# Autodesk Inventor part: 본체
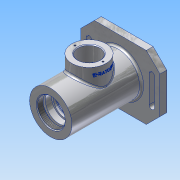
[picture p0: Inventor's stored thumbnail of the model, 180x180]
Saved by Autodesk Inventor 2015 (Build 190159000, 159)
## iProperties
Created: 2017-10
Part Number: 본체
Material: 알루미늄 6061
Document SubType Name: Modeling
Designer: Administrator
Density: 2.7 g/cm^3
Appearance: 알루미늄 - 평지
Mass: 737.992 g
Surface Area: 652.652 cm^2
Volume: 273.33 cm^3
Author: Administrator
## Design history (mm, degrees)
sketch "스케치1"
  geometry: C1 r 31 at (0, 0); 1 further point
  constraints: 1 centre point, 1 coincident
  dimensions: "d0" = 62 diameter of C1
extrude "돌출1" new body sketch "스케치1" stored distance "d1" = 115; taper "d2" = 0 deg
sketch "스케치2"
  geometry: L1 (47, 58)-(-47, 58); L2 (-47, 58)-(-47, -58); L3 (-47, -58)-(47, -58); L4 (47, -58)-(47, 58); 3 further points
  constraints: 8 end point, 2 midpoint, 2 parallel, 1 horizontal, 1 horizontal alignment, 1 perpendicular, 1 vertical alignment
  dimensions: "d3" = 94 distance between parallel lines of L2 L4; "d4" = 116 distance between parallel lines of L3 L1
extrude "돌출2" join sketch "스케치2" distance "d5" = 13; taper "d6" = 0 deg
sketch "스케치3"
  geometry: L1 (47, 58)-(-47, 58) reference; L2 (-47, 58)-(-47, -58) reference; L3 (-47, -58)-(47, -58) reference; L4 (47, -58)-(47, 58) reference; C1 r 35 at (0, 0); 1 further point
  constraints: 1 centre point, 1 coincident
  dimensions: "d7" = 70 diameter of C1
extrude "돌출3" cut sketch "스케치3" distance "d8" = 3; taper "d9" = 0 deg
node "작업 평면1"
sketch "스케치4"
  geometry: L1 (31, 57.5)-(-31, 57.5) reference; C1 r 25 at (0, 1.5); 1 further point
  constraints: 1 centre point, 1 vertical alignment
  dimensions: "d11" = 50 diameter of C1; "d12" = 56 distance from line of C1.centre L1
extrude "돌출4" join sketch "스케치4" stored distance "d13" = 3; taper "d14" = 0 deg
sketch "스케치5"
  geometry: L1 (-35, -57.5)-(35, -57.5) reference; L2 (22, -57.5)-(16, -43.5); L3 (16, -43.5)-(12.5, -43.5); L4 (12.5, -43.5)-(12.5, -36.2); L5 (12.5, -36.2)-(10, -36.2); L6 (10, -36.2)-(10, -33.5); L7 (10, -33.5)-(0, -33.5); L8 (0, -33.5)-(0, -57.5); 1 further point
  constraints: 14 end point, 3 perpendicular, 1 midpoint, 1 parallel, 1 point on line, 1 vertical
  dimensions: "d16" = 24 distance of L7.end L8.end; "d18" = 32 diameter of L2.end L8; "d19" = 14 vertical distance of L2.start L2.end; "d20" = 2.7 distance from line of L5.end L7; "d21" = 20 diameter of L6 L8; "d22" = 44 diameter of L2.start L8; "d23" = 25 diameter of L4 L8; "d24" = 7.3 distance of L3.end L4.end (derived)
revolve "회전1" sketch "스케치5" stored, may be unused: angle "d25" = 90 deg
sketch "스케치6"
  geometry: 2 further points
  constraints: 1 coincident
hole "구멍1" sketch "스케치6" at (0, 0) diameter "d26" = 40.376; stored, may be unused: countersink angle "d30" = 90 deg, drill point angle "d32" = 0 deg; dims "d27" = 84, "d28" = 4, "d29" = 2, "d31" = 9
sketch "스케치7"
  geometry: L1 (24, 48.5)-(24, 45.5); L2 (24, 45.5)-(20, 45.5); L3 (20, 45.5)-(20, 36.5); L4 (20, 36.5)-(17.5, 36.5); L5 (17.5, 36.5)-(17.5, 33.25); L6 (17.5, 33.25)-(18.5, 33.25); L7 (18.5, 33.25)-(18.5, 31.5); L8 (18.5, 31.5)-(17.5, 31.5); L9 (17.5, 31.5)-(17.5, 20.5); L10 (17.5, 20.5)-(26, 20.5); L11 (26, 20.5)-(26, -17.5); L12 (26, -17.5)-(17.5, -17.5); L13 (17.5, -17.5)-(17.5, -28.5); L14 (17.5, -28.5)-(16.5, -28.5); L15 (16.5, -28.5)-(16.5, -33.5); L16 (0, 48.5)-(0, -33.5); L17 (24, 48.5)-(0, 48.5); L18 (20.188, 48.5)-(-20.188, 48.5) reference; L19 (16.5, -33.5)-(0, -33.5); L20 (10, -33.5)-(-10, -33.5) reference; L21 (-20.188, 57.5)-(20.188, 57.5) reference; 2 further points
  constraints: 36 end point, 13 perpendicular, 3 midpoint, 2 point on line, 1 collinear, 1 horizontal, 1 vertical alignment
  dimensions: "d33" = 48 diameter of L1 L16; "d34" = 82 distance of L16.end L16.start; "d35" = 3 distance of L1.start L1.end; "d36" = 40 diameter of L3 L16; "d37" = 35 diameter of L5 L16; "d39" = 52 diameter of L11 L16; "d40" = 35 diameter of L13 L16; "d41" = 33 diameter of L15 L16; "d42" = 5 distance from line of L19 L13.end; "d43" = 11 distance from line of L14 L11.end; "d44" = 38 distance of L10.end L11.end; "d47" = 21 distance from line of L21 L3.end; "d48" = 1.75 distance of L6.end L7.end; "d49" = 26 distance from line of L21 L7.end; "d50" = 11 distance of L9.end L8.end (derived); "d51" = 37 diameter of L7 L16
revolve "회전2" sketch "스케치7" stored, may be unused: angle "d52" = 90 deg
fillet "모깎기1" dims "d53" = 0.3
fillet "모깎기2" dims "d54" = 3
fillet "모깎기3" dims "d55" = 3
fillet "모깎기4" dims "d56" = 3
chamfer "모따기1" distance "d57" = 1; stored, may be unused: second distance "d58" = 2, angle "d59" = 45 deg
fillet "모깎기5" dims "d60" = 0.3
chamfer "모따기2" distance "d61" = 0.7; stored, may be unused: second distance "d62" = 2, angle "d63" = 30 deg
chamfer "모따기3" distance "d64" = 20; stored, may be unused: second distance "d65" = 2, angle "d66" = 30 deg
sketch "스케치8"
  geometry: 1 further point
sketch "스케치9"
  geometry: L1 (-20, 50)-(20, 50); L2 (20, 42)-(-20, 42); A1 r 4 centre (20, 46) between (20, 42) and (20, 50); A2 r 4 centre (-20, 46) between (-20, 50) and (-20, 42); 2 further points
  constraints: 4 end point, 4 point on circle, 4 tangent, 2 centre point, 1 horizontal, 1 midpoint, 1 parallel, 1 vertical alignment
  dimensions: "d67" = 40 distance of A2.centre A1.centre; "d68" = 4 radius of A1; "d69" = 46 vertical distance of point (0, 0) A2.centre
extrude "돌출5" cut sketch "스케치9" stored distance "d70" = 3; taper "d71" = 0 deg
fillet "모깎기6" dims "d72" = 3
node "작업 평면2"
sketch "스케치10"
  geometry: L1 (-16, 56)-(-78, 56) reference; L2 (0, -25)-(0, 25) reference; 3 further points
  constraints: 1 coincident, 1 other
  dimensions: "d73" = 56 distance from line of point (-10, 0) L1; "d74" = 10 distance from line of point (-10, 0) L2
feature "엠보싱1" sketch "스케치10" dims "d9" = 0, "d75" = 0.5, "d76" = 0
sketch "스케치11"
  geometry: C1 r 25 at (0, 0) reference; C2 r 16 at (0, 0); 1 further point
  constraints: 1 centre point, 1 coincident
  dimensions: "d78" = 32 diameter of C2
extrude "돌출6" cut sketch "스케치11" stored distance "d79" = 3; taper "d80" = 0 deg
sketch "스케치12" dims "d81" = 41
  geometry: C1 r 25 at (0, 0) reference; 3 further points
  constraints: 2 vertical alignment, 1 coincident, 2 other
hole "구멍2" sketch "스케치12" at (0, -20.5) diameter "d82" = 2.459; stored, may be unused: countersink angle "d86" = 90 deg, drill point angle "d88" = 120 deg; dims "d83" = 6, "d84" = 4, "d85" = 2, "d87" = 8
fillet "모깎기7" dims "d92" = 3
chamfer "모따기4" distance "d93" = 1; stored, may be unused: second distance "d94" = 2, angle "d95" = 30 deg
node "솔리드1"
mirror "대칭1"
pattern_circular "원형 패턴1" dims angle "d90" = 360 deg
node "투영된 루프1"
other parameters: "d10" = -47
